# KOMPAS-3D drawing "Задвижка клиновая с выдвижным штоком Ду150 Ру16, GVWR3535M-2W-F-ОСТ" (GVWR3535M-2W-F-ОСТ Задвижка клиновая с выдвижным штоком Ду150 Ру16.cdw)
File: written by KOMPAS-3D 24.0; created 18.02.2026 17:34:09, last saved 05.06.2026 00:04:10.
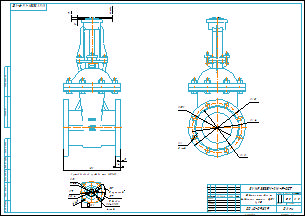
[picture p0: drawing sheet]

Document properties: art: D040-10013; Автор: R2D2; Форматы листов документа: A2; Полное имя файла: GVWR3535M-2W-F-ОСТ Задвижка клиновая с выдвижным штоком Ду150 Ру16.m3d; Масса: 47.5; Наименование: Задвижка клиновая с выдвижным штоком Ду150 Ру16; Количество листов документа: 1; Примечание: D040-09829

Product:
- Part/product: Задвижка клиновая с выдвижным штоком Ду150 Ру16  | designation GVWR3535M-2W-F-ОСТ
    Масса: 47.5
    Раздел спецификации: Прочие изделия
    Примечание: D040-09829
    additional columns: D040-10013

Views: Проекционный вид 3
Referenced files in E:\Работа\Зайцев\Для компаса\: чертеж DN.ru А3.cdt
Referenced files in E:\Работа\Зайцев\GVWR3535M-2W-F-ОСТ Задвижка клиновая 30нж941нж DN.ru Ду50-200 Ру16\исходные данные\DN150\dn150\: GVWR3535M-2W-F-ОСТ Задвижка клиновая с выдвижным штоком Ду150 Ру16.m3d
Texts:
  Присоединение привода тип АК (А)
  чертеж DN.ru А3.cdt
  Задвижка клиновая с
  выдвижным штоком Ду150
  Ру16
  GVWR3535M-2W-F-ОСТ
  Задвижка клиновая с выдвижным штоком Ду150 Ру16
  GVWR3535M-2W-F-ОСТ Задвижка клиновая с выдвижным штоком Ду150 Ру16
Dimensions and other numbers on the sheet: 100; 5 кулачков; 5 впадин; 14 (М12); 4 отв.; 13,5; 104; 70; 44; 32; 1:2,5; 0; 1; 2; 47,5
